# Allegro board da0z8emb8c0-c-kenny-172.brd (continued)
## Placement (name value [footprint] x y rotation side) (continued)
HOLE7  *spad-c354np  [SPAD-C354NP]  140.49 22.1 0 top
HOLE8  *HG-Z8E-EDADOC-3  [HG-Z8E-EDADOC-3]  86.2 15.5 0 top
HOLE10  EV@O-Z8E-1P2  [O-Z8E-1P2]  97.53 123.31 180 bottom
HOLE11  *hg-o335x315d252x232p2  [HG-O335X315D252X232P2]  11.25 109.2 180 bottom
HOLE13  *SPAD-A3A5-EDADOC-1  [SPAD-A3A5-EDADOC-1]  63.15 126.75 0 top
HOLE14  *H-TC154IC154BC237D154PT-1  [H-TC154IC154BC237D154PT-1]  78.57 83 0 top
HOLE15  EV@O-Z8E-1P2  [O-Z8E-1P2]  126.53 84.31 180 bottom
HOLE16  *hg-c354i158d118p2  [HG-C354I158D118P2]  17.48 68.15 180 bottom
HOLE17  *H-TC154IC154BC237D154PT-1  [H-TC154IC154BC237D154PT-1]  117.22 57 0 top
HOLE18  *HG-C276D126P2  [HG-C276D126P2]  221.2 48.5 180 bottom
HOLE19  *H-TC154IC154BC237D154PT-1  [H-TC154IC154BC237D154PT-1]  78.57 31 0 top
HOLE20  *h-c75d75n  [H-C75D75N]  4.2 24 180 bottom
HOLE21  h-davidoff-1  [H-DAVIDOFF-1]  216.8 21.88 180 bottom
HOLE22  *HG-Z8E-EDADOC-1  [HG-Z8E-EDADOC-1]  148.07 124.5 0 top
HOLE23  *H-DAVIDOFF-1-1  [H-DAVIDOFF-1-1]  5.2 4.4 180 bottom
HOLE24  *2D-BARCODE-8X8-S  [2D-BARCODE-8X8-S]  67.24 73.27 270 bottom
HOLE25  *2D-BARCODE-6X6-S  [2D-BARCODE-6X6-S]  21.27 99.94 0 top
HOLE26  *SPAD-RE3_5X5_0  [SPAD-RE3_5X5_0]  3.35 108.2 180 bottom
J1  *JUMP  [JOPEN25X30_S]  100.34 27.49 180 bottom
L6  BLM15AG121SN1D  [R0402]  166.18 31.86 270 top
L7  HCB2012KF-220T60  [R0805]  204.28 29.36 270 top
L9  BLM15AG121SN1D  [R0402]  186.62 16.24 180 top
L10  BLM15AG121SN1D  [R0402]  186.62 19.04 0 top
L11  BLM15AG601SN1D  [R0402]  41.08 103.49 90 bottom
L12  BLM15AG601SN1D  [R0402]  42.12 103.49 90 bottom
L13  HCB1608KF-121T30  [R0603]  204.28 19.54 270 bottom
L14  PBY160808T-600Y-N  [R0603]  201.74 18.15 180 bottom
L15  HCB1005KF-330T30  [R0402]  72.32 23.23 90 bottom
L16  HCB1005KF-330T30  [R0402]  75.5 23.23 90 bottom
NOREF  -  []  165.2 -14.93 0 top
NOREF#2  -  []  5.68 -31.69 0 top
NOREF#3  -  [unnamed#2]  39.81 112.76 0 top
NOREF#4  -  [unnamed#2]  14.29 3.42 0 top
NOREF#5  -  [unnamed#2]  216.6 44.31 0 top
NOREF#6  -  []  137.98 46 0 top
NOREF#7  -  [unnamed#2]  16.57 114.41 180 bottom
NOREF#8  -  [unnamed#2]  10.86 9 180 bottom
NOREF#9  -  [unnamed#2]  141.67 119.37 180 bottom
NOREF#10  -  []  170.11 31.52 180 bottom
PC1  1u/10V_4  [C0402]  65.68 125.08 90 top
PC2  10u/10V_4  [C0402_2]  66.75 125.08 270 top
PC3  0.1u/25V_4  [C0402]  68.7 125.09 270 top
PC6  0.047u/50V_6  [C0603]  44.26 120.03 0 top
PC7  *22u/6.3V_6  [C0603]  49.3 122.14 0 top
PC8  1000p/50V_4  [C0402]  41.21 121.4 180 top
PC10  0.1u/25V_4  [C0402]  68.69 121.79 90 top
PC11  10u/25V_6  [C0603]  72.7 122.14 270 top
PC12  10u/25V_6  [C0603]  71.29 122.14 270 top
PC14  2200p/50V_4  [C0402]  13.3 116.65 270 top
PC15  0.47u/10V_4  [C0402]  68.11 119.11 90 top
PC16  10u/6.3V_4  [C0402_2]  64.64 120.98 180 bottom
PC18  10u/6.3V_4  [C0402_2]  64.8 118.42 180 top
PC66  22u/6.3V_6  [C0603]  150.39 37.8 270 bottom
PC67  *22u/6.3V_6  [C0603]  157.52 34.64 270 bottom
PC69  *22u/6.3V_6  [C0603]  147.75 33.33 0 top
PC70  10p/50V_4  [C0402]  145.88 36.07 90 top
PC71  0.1u/16V_4  [C0402]  144.86 36.47 180 bottom
PC72  0.1u/16V_4  [C0402]  149.2 37.35 270 bottom
PC73  100p/50V_4  [C0402]  136.99 33.01 180 top
PC74  0.1u/50V_4  [C0402]  132.37 33.92 90 top
PC76  0.1u/50V_4  [C0402]  133.33 33.92 270 top
PC77  *100p/50V_4  [C0402]  136.99 32.05 180 top
PC78  0.1u/16V_4  [C0402]  20.89 30.47 180 top
PC79  0.1u/16V_4  [C0402]  143.93 35.22 90 top
PC80  2.2u/10V_4  [C0402]  131.99 30.58 90 top
PC81  10u/6.3V_6  [C0603]  21.78 29.83 180 bottom
PC82  1u/25V_4  [C0402]  22.67 30.42 0 top
PC86  2200p/50V_4  [C0402]  127.51 33.75 90 bottom
PC87  *0.1u/16V_4  [C0402]  25.21 29.32 180 top
PC88  1u/25V_4  [C0402]  157.12 29.86 90 top
PC90  1u/25V_4  [C0402]  152.73 29.86 90 top
PC91  *0.01u/50V_4  [C0402]  122.03 28.86 270 top
PC92  1000p/50V_4  [C0402]  19.24 28.13 0 top
PC93  0.1u/16V_4  [C0402]  25.21 28.31 180 top
PC96  0.01u/50V_4  [C0402]  134.08 28.56 90 top
PC98  1000p/50V_4  [C0402]  19.24 27.04 0 top
PC99  *0.1u/16V_4  [C0402]  25.21 27.29 180 top
PC101  1u/25V_4  [C0402]  25.21 26.28 180 top
PC103  0.1u/16V_4  [C0402]  21.91 25.69 180 top
PC104  *2200p/50V_4  [C0402]  69.78 89.01 0 bottom
PC105  10u/6.3V_6  [C0603]  21.27 27.8 270 bottom
PC106  10u/6.3V_6  [C0603]  157.41 26.78 180 top
PC108  0.1u/16V_4  [C0402]  157.54 28.05 180 top
PC109  0.1u/16V_4  [C0402]  152.72 27.82 270 top
PC110  1000p/50V_4  [C0402]  153.58 27.8 0 bottom
PC111  1000p/50V_4  [C0402]  156.26 27.8 180 bottom
PC112  10u/6.3V_6  [C0603]  151.54 28.27 270 top
PC113  22u/6.3V_6  [C0603]  31.38 15.74 90 bottom
PC114  *22u/6.3V_6  [C0603]  28.13 15.48 90 bottom
PC115  *680p/50V_6  [C0603]  44.56 22.32 180 bottom
PC116  0.1u/25V_4  [C0402]  41.49 16.67 0 bottom
PC117  2200p/50V_4  [C0402]  125.36 30.5 180 top
PC118  0.1u/50V_4  [C0402]  125.36 31.46 180 top
PC119  22u/6.3V_6  [C0603]  29.97 15.74 90 bottom
PC120  *22u/6.3V_6  [C0603]  35.88 15.02 0 bottom
PC121  22u/6.3V_6  [C0603]  32.79 15.82 90 bottom
PC122  *47p/50V_4  [C0402]  105.42 20.41 90 top
PC123  *47p/50V_4  [C0402]  103.69 21.32 90 top
PC125  *1u/10V_4  [C0402]  66.27 125.1 90 bottom
PC126  *1u/10V_4  [C0402]  68.66 125.11 90 bottom
PC128  *22u/6.3V_6  [C0603]  60.83 124.64 90 top
PC129  22u/6.3V_6  [C0603]  61.99 122.62 0 top
PC130  22u/6.3V_6  [C0603]  53.91 124.32 270 bottom
PC131  22u/6.3V_6  [C0603]  52.26 124.32 270 bottom
PC132  22u/6.3V_6  [C0603]  55.51 124.32 270 bottom
PC133  22u/6.3V_6  [C0603]  57.08 124.32 270 bottom
PC135  EV@0.1u/16V_4  [C0402]  120.33 83.81 180 bottom
PC136  *680p/50V_6  [C0603]  62.01 123.29 90 bottom
PC137  22u/6.3V_6  [C0603]  49.29 122.14 0 bottom
PC138  2200p/50V_4  [C0402]  69.07 120.07 270 top
PC139  0.1u/25V_4  [C0402]  59.93 119.75 0 top
PC140  10u/25V_6  [C0603]  69.87 122.24 270 top
PC142  *10u/6.3V_4  [C0402_2]  64.64 119.8 180 bottom
PC143  0.1u/50V_4  [C0402]  40.19 119.62 90 bottom
PC145  0.1u/50V_4  [C0402]  12.28 116.65 270 top
PC164  0.1u/16V_4  [C0402]  115.76 34.78 90 bottom
PC221  2200p/50V_4  [C0402]  140.44 29.62 180 bottom
PC224  22u/6.3V_6  [C0603]  147.75 30.51 0 top
PC225  22u/6.3V_6  [C0603]  147.75 31.92 0 top
PC226  22u/6.3V_6  [C0603]  151.8 37.8 270 bottom
PC227  4.7u/6.3V_4  [C0402_2]  146.31 36.09 270 bottom
PC229  0.1u/25V_4  [C0402]  148.17 35.95 90 bottom
PC233  10u/25V_8  [C0805]  140.84 32.04 0 bottom
PC234  1u/10V_4  [C0402]  144.86 35.51 0 bottom
PC235  100p/50V_4  [C0402]  138 33.97 180 top
PC236  2200p/50V_4  [C0402]  106.17 24.42 90 bottom
PC237  0.1u/50V_4  [C0402]  132.27 34.68 0 bottom
PC238  0.47u/25V_6  [C0603]  129.52 33.96 0 bottom
PC239  10u/25V_8  [C0805]  142.29 29.45 90 bottom
PC240  10u/25V_8  [C0805]  126.03 33.92 90 bottom
PC241  22u/25V_8  [C0805]  107.66 24.23 90 bottom
PC242  *0.1u/16V_4  [C0402]  135.44 29.15 0 top
PC243  0.047u/50V_6  [C0603]  129.52 32.55 0 bottom
PC244  0.1u/25V_4  [C0402]  140.44 30.58 180 bottom
PC245  0.1u/25V_4  [C0402]  138.65 40.83 270 top
PC246  22u/25V_8  [C0805]  110.26 23.6 0 bottom
PC247  *680p/50V_6  [C0603]  144.72 30.08 0 bottom
PC248  0.1u/25V_4  [C0402]  130.38 28.99 180 bottom
PC249  *680p/50V_6  [C0603]  127.03 29.23 270 bottom
PC250  *0.1u/16V_4  [C0402]  153.58 28.91 0 bottom
PC251  0.1u/16V_4  [C0402]  154.92 28.53 90 bottom
PC252  *0.1u/16V_4  [C0402]  156.65 29.83 180 bottom
PC253  0.1u/25V_4  [C0402]  128.77 28.16 270 bottom
PC254  0.1u/25V_4  [C0402]  130.38 27.78 180 bottom
PC256  0.1u/50V_4  [C0402]  104.25 24.42 270 bottom
PC258  *100p/50V_4  [C0402]  105.21 24.42 90 bottom
PC261  2200p/50V_4  [C0402]  47.39 15.69 90 bottom
PC262  0.1u/25V_4  [C0402]  46.84 18.94 270 bottom
PC263  0.1u/25V_4  [C0402]  47.8 18.94 90 bottom
PC264  10u/25V_8  [C0805]  49.27 19.62 270 bottom
PC265  1u/10V_4  [C0402]  43.73 15.8 90 bottom
PC266  4.7u/10V_4  [C0402]  43.05 19.38 270 top
PC267  0.1u/16V_4  [C0402]  46.43 15.46 90 bottom
PC268  0.1u/16V_4  [C0402]  32.19 24.98 90 bottom
PC269  22u/6.3V_6  [C0603]  31.97 22.79 270 bottom
PC270  10u/25V_8  [C0805]  47.29 21.42 270 bottom
PC271  0.1u/16V_4  [C0402]  46.66 17.35 0 bottom
PC272  10p/50V_4  [C0402]  45.09 15.08 0 bottom
PC551  *2200p/50V_6  [C0603]  37.02 23.56 0 top
PC561  0.1u/6.3V_2  [C0201]  34.35 25.01 270 top
PC562  22u/6.3V_6  [C0603]  32.95 27.93 270 top
PC563  22u/6.3V_6  [C0603]  34.48 27.93 270 top
PC571  10u/6.3V_4  [C0402_2]  44 27.29 270 top
PC572  0.01u/50V_4  [C0402]  45.27 27.29 270 top
PC574  *22p/50V_4  [C0402]  39.56 23.23 270 top
PC581  *0.1u/6.3V_2  [C0201]  39.18 25.51 0 top
PC2000  *0.01u/50V_4  [C0402]  145.33 39.58 270 bottom
PC2001  *0.1u/25V_4  [C0402]  146.69 40.83 90 top
PC2002  2200p/50V_4  [C0402]  145.73 40.83 90 top
PC2003  10u/25V_8  [C0805]  142.28 38.96 0 bottom
PC2004  10u/6.3V_6  [C0603]  143.12 46.24 0 bottom
PC2005  0.1u/25V_4  [C0402]  138.53 46.02 270 bottom
PC2006  22u/6.3V_6  [C0603]  136.74 47.27 0 bottom
PC2007  22u/6.3V_6  [C0603]  134.52 38.15 90 bottom
PC2008  22u/6.3V_6  [C0603]  133.83 47.27 180 bottom
PC2009  22u/6.3V_6  [C0603]  133.1 38.15 90 bottom
PC2010  22u/6.3V_6  [C0603]  137.34 38.15 90 bottom
PC2011  *22u/6.3V_6  [C0603]  135.93 38.15 90 bottom
PC2012  *22u/6.3V_6  [C0603]  131.69 38.15 90 bottom
PC2013  0.1u/16V_4  [C0402]  130.5 38.6 90 bottom
PC2014  *1000p/50V_4  [C0402]  147.38 40.25 90 bottom
PC2015  *680p/50V_6  [C0603]  139.36 37.53 180 bottom
PC2016  *0.047u/6.3V_2  [C0201]  146.87 44.54 90 bottom
PC2017  0.047u/6.3V_2  [C0201]  145.1 45.53 90 bottom
PC5357  EV@10u/6.3V_6  [C0603]  120.46 85.08 0 bottom
PC5359  EV@0.1u/16V_4  [C0402]  106.49 83.68 90 bottom
PC6000  *1000p/25V_2  [C0201]  144.78 56.08 270 bottom
PC6001  2.2u/10V_4  [C0402]  150.97 54.63 0 top
PC6002  2.2u/10V_4  [C0402]  141.07 54.39 180 top
PC6003  0.1u/25V_4  [C0402]  145.61 56.04 90 bottom
PC6004  0.1u/25V_4  [C0402]  141.07 55.35 0 top
PC6005  0.1u/16V_4  [C0402]  147.53 57.95 180 top
PC6006  0.1u/6.3V_2  [C0201]  146.45 56.01 270 bottom
PC6007  82p/50V_4  [C0402]  145.81 57.95 180 top
PC6008  150p/50V_4  [C0402]  146.04 57.86 180 bottom
PC6009  0.1u/25V_4  [C0402]  141.45 53.05 90 top
PC6010  1u/6.3V_4  [C0402]  147.28 55.92 90 bottom
PC6011  0.1u/16V_4  [C0402]  149.2 49.61 270 top
PC6012  0.1u/6.3V_2  [C0201]  148.55 51.1 0 bottom
PC6013  0.1u/25V_4  [C0402]  141.42 51.32 90 top
PC6014  0.1u/16V_4  [C0402]  147.85 49.23 0 top
PC6015  82p/50V_4  [C0402]  146.13 49.5 180 top
PC6016  150p/50V_4  [C0402]  146.61 47.85 270 bottom
PC6017  *100p/50V_4  [C0402]  149.25 51.94 0 bottom
PC6018  *82p/50V_4  [C0402]  146.96 51.72 0 bottom
PC6019  0.47uF/6.3V_2  [C0201]  148.84 52.78 180 bottom
PC6020  *100p/50V_4  [C0402]  148.92 54.57 0 bottom
PC6021  10u/25V_8  [C0805]  140.26 48.4 0 bottom
PC6022  10u/25V_8  [C0805]  143.53 49.94 180 bottom
PC6023  *10u/25V_8  [C0805]  143.53 47.97 180 bottom
PC6024  2200p/50V_4  [C0402]  136.62 60.15 0 top
PC6025  0.1u/25V_4  [C0402]  136.63 61.12 0 top
PC6026  *15u/25V_7343H1.9  [CC7343]  121.93 41.17 90 bottom
PC6027  330u/2V_7343H1.9  [CC7343]  123.81 50.67 270 bottom
PC6028  330u/2V_7343H1.9  [CC7343]  118.26 63.87 180 bottom
PC6029  330u/2V_7343H1.9  [CC7343]  116.11 70.97 90 bottom
PC6030  *330u/2V_7343H1.9  [CC7343]  132.13 52.49 0 top
PC6031  *2200p/50V_4  [C0402]  133.06 59.58 90 top
PC6032  10u/25V_8  [C0805]  138.54 55.78 0 bottom
PC6033  10u/25V_8  [C0805]  141.79 60.64 180 bottom
PC6034  *10u/25V_8  [C0805]  139.86 63.23 270 bottom
PC6035  2200p/50V_4  [C0402]  137.44 53.9 90 top
PC6036  0.1u/25V_4  [C0402]  138.97 49.66 0 top
PC6037  *22u/6.3V_6  [C0603]  101.53 58.63 180 top
PC6038  *22u/6.3V_6  [C0603]  99.12 58.13 90 top
PC6039  *22u/6.3V_6  [C0603]  100.77 60.44 180 top
PC6040  *22u/6.3V_6  [C0603]  98.11 54.47 180 top
PC6041  22u/6.3V_6  [C0603]  101.15 54.27 180 top
PC6042  22u/6.3V_6  [C0603]  101.53 57.11 180 top
PC6043  *22u/6.3V_6  [C0603]  99.5 52.69 180 top
PC6044  *22u/6.3V_6  [C0603]  104.23 57.01 90 top
PC6045  22u/6.3V_6  [C0603]  101.54 55.68 180 top
PC6046  22u/6.3V_6  [C0603]  105.65 57.01 90 top
PC6047  *2200p/50V_4  [C0402]  137.79 48.45 180 bottom
PC6048  10u/25V_8  [C0805]  125.9 68.83 270 bottom
PC6049  10u/25V_8  [C0805]  134.34 63.77 180 bottom
PC6050  *10u/25V_8  [C0805]  127.88 68.83 270 bottom
PC6051  2200p/50V_4  [C0402]  123.48 68.51 270 bottom
PC6052  0.1u/25V_4  [C0402]  124.44 68.51 270 bottom
PC6053  330u/2V_7343H1.9  [CC7343]  126.85 75.22 270 bottom
PC6054  *330u/2V_7343H1.9  [CC7343]  134.79 75.68 0 top
PC6055  *22u/6.3V_6  [C0603]  92.39 81.52 270 top
PC6056  *22u/6.3V_6  [C0603]  118.48 81.65 270 top
PC6057  *22u/6.3V_6  [C0603]  89.09 81.65 270 bottom
PC6058  *22u/6.3V_6  [C0603]  91.93 81.65 270 bottom
PC6059  *22u/6.3V_6  [C0603]  107.25 81.27 270 bottom
PC6060  *22u/6.3V_6  [C0603]  111.62 81.27 270 bottom
PC6061  *22u/6.3V_6  [C0603]  90.51 81.65 270 bottom
PC6062  *22u/6.3V_6  [C0603]  119.9 81.65 270 top
PC6063  *22u/6.3V_6  [C0603]  108.77 81.27 270 bottom
PC6064  *22u/6.3V_6  [C0603]  110.2 81.27 270 bottom
PC6065  *2200p/50V_4  [C0402]  139.09 73.9 270 bottom
PC6229  0.47u/6.3V_4  [C0402]  192.39 26.15 180 top
PC6230  10u/6.3V_6  [C0603]  195.26 16.12 90 top
PC6231  0.1u/16V_4  [C0402]  193.99 16.37 90 top
PC9000  EV@0.47uF/6.3V_2  [C0201]  66.93 112.36 180 bottom
PC9001  EV@2.2u/10V_4  [C0402]  66.49 114.18 180 bottom
PC9002  EV@2.2u/10V_4  [C0402]  78.13 112.52 0 bottom
PC9003  EV@0.1u/25V_4  [C0402]  76 116.43 270 bottom
PC9004  *SP@0.1u/25V_4  [C0402]  77.55 113.86 270 bottom
PC9005  *SP@0.1u/6.3V_2  [C0201]  71.64 116.04 180 bottom
PC9006  EV@0.1u/6.3V_2  [C0201]  72.32 118.55 270 bottom
PC9007  *SP@82p/50V_4  [C0402]  74.66 115.85 0 bottom
PC9008  *SP@150p/50V_4  [C0402]  74.59 117.77 0 bottom
PC9009  *EV@1000p/50V_4  [C0402]  75.93 118.46 90 bottom
PC9010  EV@0.1u/25V_4  [C0402]  78.13 111.26 180 bottom
PC9011  EV@1u/6.3V_2  [C0201]  71.18 117.21 180 bottom
PC9012  EV@0.1u/16V_4  [C0402]  68.92 107.08 270 bottom
PC9013  EV@0.1u/6.3V_2  [C0201]  68.52 103.94 0 bottom
PC9014  EV@0.1u/25V_4  [C0402]  76.4 107.57 0 bottom
PC9015  EV@0.1u/16V_4  [C0402]  70.85 107.08 90 bottom
PC9016  EV@82p/50V_4  [C0402]  73.1 106.97 270 bottom
PC9017  EV@150p/50V_4  [C0402]  72.91 105.21 270 bottom
PC9018  *EV@100p/50V_4  [C0402]  67.28 111.3 0 bottom
PC9019  *EV@82p/50V_4  [C0402]  74.06 107 270 bottom
PC9020  *EV@100p/50V_4  [C0402]  67.31 113.22 0 bottom
PC9021  EV@10u/25V_8  [C0805]  81.57 111.76 180 bottom
PC9022  EV@10u/25V_8  [C0805]  78.75 97.7 180 bottom
PC9023  *EV@10u/25V_8  [C0805]  76.46 95.73 180 bottom
PC9024  EV@2200p/50V_4  [C0402]  73.99 94.32 0 bottom
PC9025  EV@0.1u/25V_4  [C0402]  73.99 95.28 0 bottom
PC9026  EV@15u/25V_7343H1.9  [CC7343]  70.78 98.69 270 bottom
PC9027  EV@0.1u/16V_4  [C0402]  92.35 101.6 0 top
PC9028  EV@330u/2V_7343H1.9  [CC7343]  88.65 114.36 180 bottom
PC9029  EV@22u/6.3V_6  [C0603]  92.34 102.79 0 top
PC9031  *EV@2200p/50V_4  [C0402]  80.99 110.39 90 top
PC9032  EV@10u/25V_8  [C0805]  75.52 97.7 0 bottom
PC9033  EV@10u/25V_8  [C0805]  76.46 93.76 180 bottom
PC9034  *EV@10u/25V_8  [C0805]  81.57 113.74 180 bottom
PC9035  EV@2200p/50V_4  [C0402]  73.99 96.24 0 bottom
PC9036  EV@0.1u/25V_4  [C0402]  79.47 113.98 270 bottom
PC9037  *EV@330u/2V_7343H1.9  [CC7343]  90.25 107.29 180 top
PC9038  EV@0.1u/16V_4  [C0402]  92.35 100.63 0 top
PC9039  EV@330u/2V_7343H1.9  [CC7343]  82.82 94.37 180 bottom
PC9040  EV@22u/6.3V_6  [C0603]  92.34 104.21 0 top
PC9041  *EV@2200p/50V_4  [C0402]  81.27 98.18 0 bottom
PC9042  *SP@10u/25V_8  [C0805]  77.4 118.99 90 bottom
PC9043  *SP@10u/25V_8  [C0805]  80.51 119.86 90 top
PC9044  *SP@10u/25V_8  [C0805]  78.54 119.86 90 top
PC9045  *SP@2200p/50V_4  [C0402]  76.1 119.54 90 top
PC9046  *SP@0.1u/25V_4  [C0402]  77.06 119.54 90 top
PC9047  *SP@0.1u/16V_4  [C0402]  90.1 124.45 0 top
PC9049  *SP@330u/2V_7343H1.9  [CC7343]  87.68 121.46 180 top
PC9050  *SP@2200p/50V_4  [C0402]  82.07 116.28 0 top
PC9065  EV@2200p/50V_4  [C0402]  146.55 67.27 270 top
PC9066  *EV@22u/6.3V_6  [C0603]  141.82 75.05 90 bottom
PC9067  *EV@0.01u/50V_4  [C0402]  142.03 63.1 180 bottom
PC9068  *EV@680p/50V_6  [C0603]  142.43 68.55 180 bottom
PC9069  EV@22u/6.3V_6  [C0603]  147.17 74.48 90 top
PC9070  EV@22u/6.3V_6  [C0603]  145.76 74.48 90 top
PC9071  *EV@22u/6.3V_6  [C0603]  140.41 75.05 90 bottom
PC9072  EV@0.1u/25V_4  [C0402]  149.09 69.6 180 bottom
PC9073  EV@22u/6.3V_6  [C0603]  148.59 74.48 90 top
PC9074  EV@10u/6.3V_6  [C0603]  149.22 65.16 270 bottom
PC9075  *EV@0.1u/25V_4  [C0402]  145.59 67.27 270 top
PC9076  EV@22u/6.3V_6  [C0603]  144.35 74.48 90 top
PC9077  EV@0.047u/6.3V_2  [C0201]  148.51 63.41 0 bottom
PC9078  EV@0.1u/16V_4  [C0402]  149.11 77.66 180 bottom
PC9079  EV@22u/6.3V_6  [C0603]  142.87 74.5 90 top
PC9080  EV@10u/25V_8  [C0805]  141.94 66.15 270 bottom
PC9091  *EV@0.1u/16V_4  [C0402]  116.9 79.36 180 bottom
PC9092  EV@0.1u/16V_4  [C0402]  117.66 80.5 180 bottom
PC9094  EV@0.22u/10V_4  [C0402]  112.84 77.71 270 bottom
PC9095  *EV@1000p/50V_4  [C0402]  142.55 62.14 0 bottom
PC9096  *EV@0.047u/6.3V_2  [C0201]  147.77 61.68 0 bottom
PC9132  10u/6.3V_6  [C0603]  196.78 16.12 90 top
PC9162  *22p/50V_4  [C0402]  192.37 28.38 0 top
PC9163  *22u/6.3V_6  [C0603]  32.95 24.88 90 top
PC9164  4.7u/6.3V_4  [C0402_2]  196.56 31.53 270 top
PC9173  *10p/50V_4  [C0402]  150.16 55.92 270 bottom
PC9174  *10p/50V_4  [C0402]  149.2 55.92 270 bottom
PC9175  *10p/50V_4  [C0402]  148.24 55.92 270 bottom
PC9176  *EV@10p/50V_4  [C0402]  70.64 121.76 0 bottom
PC9177  *EV@10p/50V_4  [C0402]  70.93 119.84 0 bottom
PC9178  *EV@10p/25V_2  [C0201]  70.65 117.99 180 bottom
PC9179  EV@1u/6.3V_4  [C0402]  116.65 82.16 90 bottom
PC9181  EV@10u/6.3V_4  [C0402_2]  107.63 83.68 90 bottom
PC9182  EV@0.1u/16V_4  [C0402]  119.06 86.73 270 bottom
PC9183  *EV@10u/6.3V_4  [C0402_2]  108.9 83.68 90 bottom
PC9185  SP@0.1u/6.3V_2  [C0201]  94.3 115.3 0 top
PC9186  SP@22u/6.3V_6  [C0603]  91.88 116.19 0 top
PC9187  SP@22u/6.3V_6  [C0603]  112.94 109.08 0 top
PC9188  *22u/6.3V_6  [C0603]  116.39 109.59 270 top
PC9189  *22p/50V_4  [C0402]  87.44 117.33 90 top
PC9190  SP@0.01u/50V_4  [C0402]  85.79 113.65 90 top
PC9191  SP@10u/6.3V_4  [C0402_2]  84.64 113.65 90 top
PC9192  *0.1u/6.3V_2  [C0201]  90.1 116.32 90 top
PD2  P4SMAFJ20A  [D-3_8X2_5]  19.62 112.51 0 top
PD4  BAT54CW  [SOT23-1_7-65-3P]  127.22 33.46 270 top
PD5  PDZ5.6B  [D-SOD323-1_7X1_25-PMEG4005AEA]  107.62 21.1 0 top
PD6  PDZ5.6B  [D-SOD323-1_7X1_25-PMEG4005AEA]  101.41 21.58 180 top
PJ1  *Short_1206  [S1206]  72.64 119.1 0 top
PJ2  *Short_3720  [SHORT3720]  152.33 33.01 270 top
PJ3  *Short_3720  [SHORT3720]  140.84 34.82 0 bottom
PJ4  *Short_3720  [SHORT3720]  30.65 19.29 270 bottom
PJ5  *Short_1206  [S1206]  52.05 120.69 90 bottom
PJ6  30738-00042-001  [DCJK-30706-00042-001-3P-SMT]  1.85 116.6 90 bottom
PJ11  50458-00801-V02  [WTB-50458-00801-V02-8P-L]  102.45 16.42 180 bottom
PJ2000  *Short_3720  [SHORT3720]  128.1 45.96 270 bottom
PJ2001  *Short_3720  [SHORT3720]  142.78 39.9 180 top
PJ7002  *Short_3720  [SHORT3720]  195.9 19.8 270 top
PJ7004  *Short_3720  [SHORT3720]  30.16 26.53 90 top
PJ7005  *Short_3720  [SHORT3720]  45.78 24.12 90 top
PJ9001  *Short_3720  [SHORT3720]  75.3 102.55 90 bottom
PJ9007  *Short_3720  [SHORT3720]  143.17 65.28 270 top
PJ9008  *Short_3720  [SHORT3720]  144.03 78.35 180 top
PJ9010  *Short_3720  [SHORT3720]  50.08 16.19 180 bottom
PL1  4.7uH/1.08A_2.5x2.0x1.2  [L2_5X2-1_2]  63.23 124.65 180 top
PL2  0.68uH/15.5A_7x7x3  [L6_6X6_6-2_8H]  55.52 122.38 180 top
PL10  1uH/11A_7x7x3  [L6_6X6_6-2_8H]  152.2 32.94 0 bottom
PL11  6.8uH/4.5A_7x7x3  [L6_6X6_6-2_8H]  117.39 30.07 180 bottom
PL13  1uH/11A_7x7x3  [L6_6X6_6-2_8H]  37.05 19.3 180 bottom
PL14  2.2uH/1.67A_2.5x2.0x1.2  [L2_5X2-1_2H]  194.88 23.61 270 top
PL551  1uH/3.35A_2.5x2.0x1.2  [L2_5X2-1_2H]  36.84 27.42 180 top
PL2000  1uH/11A_7x7x3  [L6_6X6_6-2_8H]  134.5 43.01 180 bottom
PL6000  0.15uH/22A_7x7x3  [L6_6X6_6-2_8H]  133.81 75.17 180 bottom
PL6001  0.15uH/22A_7x7x3  [L6_6X6_6-2_8H]  127.61 60.01 180 bottom
PL6002  0.15uH/22A_7x7x3  [L6_6X6_6-2_8H]  130.76 52.83 180 bottom
PL9000  EV@0.22uH/23A_7x7x3  [L6_6X6_6-2_8H]  88.31 101.26 0 bottom
PL9001  EV@0.22uH/23A_7x7x3  [L6_6X6_6-2_8H]  89.79 108.45 0 bottom
PL9002  *SP@1uH/11A_7x7x3  [L6_6X6_6-2_8H]  88.45 120.28 0 bottom
PL9005  EV@1uH/11A_7x7x3  [L6_6X6_6-2_8H]  146.08 73.63 90 bottom
PL9006  SP@1uH/3.35A_2.5x2.0x1.2  [L2_5X2-1_2H]  92.01 113.91 0 top
PQ3  AONS32306  [POWER-5_67X4_8-1_27-5P]  39.05 117.97 0 top
PQ4  AONS32306  [POWER-5_67X4_8-1_27-5P]  47.18 116.57 180 top
PQ7  2N7002K  [SOT23-2-95-3P]  76.9 90.16 180 bottom
PQ8  DDTC144EUA-7-F  [SOT23-1_7-65-3P]  73.47 89.27 0 bottom
PQ9  2N7002KW  [SOT23-1_7-65-3P]  138.66 35.82 180 top
PQ10  2N7002K  [SOT23-2-95-3P]  125.79 37.71 180 top
PQ11  AONS32306  [POWER-5_2X5_55-1_27-5P]  118.73 32.04 270 top
PQ12  2N7002K  [SOT23-2-95-3P]  142.48 31.14 270 top
PQ13  2N7002K  [SOT23-2-95-3P]  47.48 16.12 90 top
PQ26  AONR32320C  [POWER-3X3-65-5P-ADNR21357]  123.02 34.28 270 bottom
PQ27  AONR32320C  [POWER-3X3-65-5P-ADNR21357]  124.14 30.14 0 bottom
PQ35  *2N7002K  [SOT23-2-95-3P]  62.15 90.54 0 bottom
PQ2000  AONS32306  [POWER-5_2X5_55-1_27-5P]  127.08 40.42 270 bottom
PQ6000  AONS36312  [POWER-5_2X5_55-1_27-5P]  137.65 68.23 270 bottom
PQ6001  AOE6932  [POWER-5X6-1_27-10P]  135.48 59.46 270 bottom
PQ6002  AOE6932  [POWER-5X6-1_27-10P]  138.62 52.09 270 bottom
PQ6003  AONS36380  [POWER-5_2X5_55-1_27-5P]  132.04 68.21 90 bottom
PQ9000  EV@AOE6932  [POWER-5X6-1_27-10P]  81.93 108.08 90 bottom
PQ9001  EV@AOE6932  [POWER-5X6-1_27-10P]  80.37 101.41 90 bottom
PQ9002  *SP@AONY36354  [POWER-5X6-1_27-7P-0_8H]  81.09 119.19 0 bottom
PQ9003  EV@AO3413  [SOT23-2_38-95-3P]  114.87 80.5 180 bottom
PQ9006  EV@2N7002K  [SOT23-2-95-3P]  110.55 78.29 270 bottom
PQ9007  EV@2N7002K  [SOT23-2-95-3P]  133.41 122.41 270 bottom
PQ9008  EV@2N7002K  [SOT23-2-95-3P]  129.86 122.16 90 bottom
PQ9013  2N7002K  [SOT23-2-95-3P]  62.18 86.98 180 bottom
PQ9014  AOSS32334C  [SOT23-2_38-95-3P]  26.35 31.86 90 top
PQ9015  2N7002K  [SOT23-2-95-3P]  67.51 86.98 180 bottom
PQ9056  *AOSS32334C  [SOT23-2_38-95-3P]  67.32 83.36 0 bottom
PQ9057  2N7002K  [SOT23-2-95-3P]  71.82 85.08 90 bottom
PQ9062  EV@2N7002K  [SOT23-2-95-3P]  144.33 70.73 0 top
PQ9063  EV@2N7002K  [SOT23-2-95-3P]  148.27 68.95 0 top
PQ9065  EV@2N7002K  [SOT23-2-95-3P]  92.9 96.76 180 top
PQ9066  EV@2N7002K  [SOT23-2-95-3P]  92.39 95.31 270 bottom
PQ9067  EV@2N7002K  [SOT23-2-95-3P]  130.24 118.48 90 bottom
PQ9068  EV@2N7002K  [SOT23-2-95-3P]  137.09 122.92 90 bottom
PQ9069  EV@2N7002K  [SOT23-2-95-3P]  130.24 118.35 90 top
PR2  *Short_0402  [S0402]  70.27 125.11 0 top
PR6  *Short_0603  [S0603]  62.1 118.65 180 top
PR8  *Short_0201  [S0201]  66.02 118.65 90 top
PR9  *Short_0402  [S0402]  69.45 118.73 180 top
PR12  0.01_1%_0612  [RC3216]  52.97 116.9 90 top
PR18  *Short_0201  [S0201]  52.67 114.45 90 top
PR19  *Short_0201  [S0201]  53.38 114.45 90 top
PR68  *Short_0603  [S0603]  148.72 36.28 90 top
PR69  1M_5%_6  [R0603]  136.44 34.8 90 top
PR70  10K_1%_4  [R0402]  145.3 34.73 180 top
PR71  1M_5%_6  [R0603]  132.41 37.36 180 top
PR72  1K_1%_4  [R0402]  146.23 37.45 0 top
PR74  100K_1%_4  [R0402]  134.29 33.92 90 top
PR75  100K_1%_4  [R0402]  134.09 35.27 180 top
PR76  *20.5K_1%_4  [R0402]  136.99 31.09 0 top
PR77  *Short_0201  [S0201]  144.75 33.89 180 top
PR78  *1K_1%_4  [R0402]  144.92 36.07 270 top
PR80  *Short_0201  [S0201]  135.41 35.66 90 bottom
PR81  20_5%_12  [R1206]  129.64 32.03 270 top
PR82  *100K_1%_2  [R0201]  142.81 29.07 180 top
PR83  10K_1%_4  [R0402]  143.76 33.2 270 top
PR84  *10K_1%_4  [R0402]  147.52 36.11 90 top
PR85  100K_5%_4  [R0402]  136.99 30.13 0 top
PR86  *0_5%_2  [R0201]  136.43 28.51 180 bottom
PR87  *Short_0805  [S0805]  18.48 29.09 0 bottom
PR88  0_5%_2  [R0201]  136.43 27.67 0 bottom
PR89  *Short_0201  [S0201]  27.11 29.32 180 top
PR90  1M_5%_4  [R0402]  102.33 23.14 180 bottom
PR92  *0_5%_2  [R0201]  141.75 28.97 270 top
PR93  *Short_0201  [S0201]  27.11 28.31 0 top
PR96  *Short_0201  [S0201]  141.04 28.97 270 top
PR97  100K_1%_4  [R0402]  133.12 28.56 270 top
PR98  316K_1%_4  [R0402]  135.42 28.18 180 top
PR99  *Short_0603  [S0603]  131.08 29.01 0 top
PR100  *Short_0201  [S0201]  27.11 27.29 0 top
PR102  22_5%_8  [R0805]  64.83 87.61 90 bottom
PR107  *Short_0805  [S0805]  149.16 27.55 0 top
PR108  10_1%_6  [R0603]  130.95 27.52 180 top
PR110  *Short_0805  [S0805]  153.58 25.16 180 top
PR111  *Short_0805  [S0805]  18.48 27.06 180 bottom
PR112  *0_5%_2  [R0201]  99.26 23.07 0 bottom
PR113  100_5%_4  [R0402]  100.61 23.14 180 bottom
PR114  *4.7_5%_6  [R0603]  41.94 22.16 180 bottom
PR115  10_1%_6  [R0603]  41.94 15.48 180 bottom
PR117  *Short_0603  [S0603]  45.09 18.65 0 top
PR118  *100K_1%_2  [R0201]  45.36 15.91 270 top
PR119  100_5%_4  [R0402]  105.79 23.08 180 bottom
PR120  100_5%_4  [R0402]  104.07 23.08 0 bottom
PR121  *0_5%_2  [R0201]  48.58 18.27 90 top
PR122  *Short_0201  [S0201]  49.34 18.27 90 top
PR123  *Short_0201  [S0201]  63.81 125.59 0 bottom
PR124  *Short_0201  [S0201]  67.11 124.8 90 bottom
PR125  *Short_0201  [S0201]  69.66 124.95 0 bottom
PR126  *0_5%_2  [R0201]  67.82 124.8 270 bottom
PR127  *Short_0805  [S0805]  58.88 123.75 90 bottom
PR128  *Short_0201  [S0201]  66.23 122.16 90 bottom
PR129  *4.7_5%_6  [R0603]  60.6 123.29 270 bottom
PR130  *Short_0603  [S0603]  62.75 119.65 270 bottom
PR131  100K_1%_2  [R0201]  65.47 122.16 90 bottom
PR132  5.1_1%_6  [R0603]  62.1 120.06 180 top
PR156  *Short_0805  [S0805]  120.58 81.9 180 bottom
PR159  EV@12.7K_1%_4  [R0402]  108.52 86.47 0 bottom
PR160  EV@10K_1%_4  [R0402]  108.52 87.49 0 bottom
PR161  *Short_0402  [S0402]  117.03 88.38 180 bottom
PR191  150_5%_4  [R0402]  110.42 31.1 180 bottom
PR193  *Short_0201  [S0201]  118.93 38.98 270 bottom
PR194  25.5K_1%_4  [R0402]  117.28 38.85 180 bottom
PR216  *220_5%_8  [R0805]  61.15 93.97 90 bottom
PR230  100K_1%_2  [R0201]  143.06 35.55 270 top
PR234  10K_1%_2  [R0201]  142.78 33.9 0 top
PR236  *Short_0201  [S0201]  148.99 38.75 0 bottom
PR237  *Short_0201  [S0201]  142.76 33.16 180 top
PR239  10_1%_6  [R0603]  147.41 37.66 0 bottom
PR244  *Short_0201  [S0201]  143.59 35.53 90 bottom
PR245  866K_1%_4  [R0402]  136.25 35.06 90 bottom
PR246  137K_1%_4  [R0402]  135.25 33.92 270 top
PR247  4.02K_1%_4  [R0402]  134.58 35.06 90 bottom
PR248  4.02K_1%_4  [R0402]  133.62 35.06 90 bottom
PR249  *Short_0201  [S0201]  137.22 34.86 0 bottom
PR250  *Short_0201  [S0201]  137.76 33.86 0 bottom
PR251  *Short_0201  [S0201]  137.76 33.15 0 bottom
PR252  *100K_1%_2  [R0201]  138.36 29.16 180 top
PR253  *Short_0201  [S0201]  137.76 31.95 0 bottom
PR254  *Short_0603  [S0603]  129.52 31.06 0 bottom
PR255  *Short_0201  [S0201]  137.76 31.24 0 bottom
PR257  *Short_0201  [S0201]  157.41 30.72 0 bottom
PR258  *4.7_5%_6  [R0603]  147.34 30.08 0 bottom
PR259  *Short_0201  [S0201]  151.78 29.01 0 bottom
PR260  *Short_0201  [S0201]  155.89 28.94 0 bottom
PR261  *Short_0201  [S0201]  131.75 28.5 0 bottom
PR264  10K_5%_4  [R0402]  138.21 29.06 180 bottom
PR265  *10K_5%_4  [R0402]  138.21 30.02 180 bottom
PR266  0.01_1%_0612  [RC3216]  111.94 26.32 180 bottom
PR267  *Short_0201  [S0201]  131.75 27.79 0 bottom
PR268  *4.7_5%_6  [R0603]  123.73 27.36 180 bottom
PR270  *Short_0201  [S0201]  115.71 26.16 0 bottom
PR271  *Short_0201  [S0201]  114.62 25.77 0 bottom
PR273  *Short_0201  [S0201]  47.42 14.03 0 bottom
PR274  *1K_1%_4  [R0402]  44.33 14.12 0 bottom
PR275  *10K_1%_4  [R0402]  45.09 16.04 0 bottom
PR276  *Short_0201  [S0201]  47.81 18.27 90 top
PR277  *Short_0201  [S0201]  41.21 14.21 0 bottom
PR278  1K_1%_4  [R0402]  46.05 14.12 180 bottom
PR279  10K_1%_4  [R0402]  44.4 16.62 270 top
PR283  15K_1%_2  [R0201]  193.99 30.72 90 top
PR284  *Short_0201  [S0201]  195.26 30.59 90 top
PR551  *2.2_5%_6  [R0603]  37.02 25.01 0 top
PR566  *Short_0402  [S0402]  39.43 24.62 180 top
PR567  10K_1%_4  [R0402]  41.97 23.99 0 top
PR568  20K_1%_2  [R0201]  40.57 23.23 90 top
PR569  *Short_0201  [S0201]  35.11 25.01 90 top
PR2000  100K_1%_2  [R0201]  145.96 45.43 0 bottom
PR2001  73.2K_1%_4  [R0402]  144.37 39.08 90 bottom
PR2002  10_5%_4  [R0402]  145.29 46.5 0 bottom
PR2003  2.2_5%_6  [R0603]  140.32 46.24 180 bottom
PR2004  *Short_0201  [S0201]  146.14 44.56 90 bottom
PR2005  *0_5%_2  [R0201]  147.51 43.5 90 bottom
PR2006  *Short_0201  [S0201]  146.54 43.5 270 bottom
PR2007  *4.7_5%_6  [R0603]  138.75 39.55 90 bottom
PR2008  10_1%_2  [R0201]  130.26 37.2 90 bottom
PR2009  *Short_0402  [S0402]  147.47 46.12 90 bottom
PR2010  11.8K_1%_4  [R0402]  146.31 41.16 270 bottom
PR2011  20K_1%_2  [R0201]  147.38 41.54 0 bottom
PR2012  *Short_0201  [S0201]  129.35 35.67 270 bottom
PR2013  *Short_0402  [S0402]  147.02 42.5 180 bottom
PR2015  *0_5%_2  [R0201]  119.19 50.53 90 top
PR2033  *10K_1%_2  [R0201]  151.06 56.63 270 bottom
PR6000  *Short_0201  [S0201]  113.47 54.22 270 bottom
PR6001  4.7_5%_4  [R0402]  150.97 53.67 0 top
PR6002  *Short_0402  [S0402]  140.08 50.62 180 top
PR6003  4.7_5%_4  [R0402]  144.69 58.07 90 bottom
PR6004  1.47K_1%_4  [R0402]  153.12 49.56 0 top
PR6005  28K_1%_4  [R0402]  151.4 49.56 0 top
PR6006  19.1K_1%_4  [R0402]  150.94 52.57 0 top
PR6007  22.6K_1%_4  [R0402]  152.72 52.41 180 bottom
PR6008  1_5%_6  [R0603]  141.52 56.54 180 top
PR6009  590_1%_4  [R0402]  152.66 50.65 0 top
PR6010  4.53K_1%_4  [R0402]  150.94 50.65 0 top
PR6011  237K_1%_4  [R0402]  152.66 52.57 0 top
PR6012  *Short_0201  [S0201]  134.15 79.21 270 bottom
PR6013  60.4K_1%_4  [R0402]  132.81 80.16 0 bottom
PR6014  *Short_0603  [S0603]  139.5 55.93 90 top
PR6015  3.74K_1%_4  [R0402]  147.53 59.87 180 top
PR6016  10K_1%_4  [R0402]  152.66 51.61 180 top
PR6017  14K_1%_4  [R0402]  150.94 51.61 180 top
PR6018  100K_NTC_4_1%  [R0402]  132.81 79.2 0 bottom
PR6019  6.04K_1%_4  [R0402]  152.84 50.41 0 bottom
PR6020  60.4K_1%_4  [R0402]  151.17 50.36 270 bottom
PR6021  *Short_0201  [S0201]  129.96 48.78 90 bottom
PR6022  60.4K_1%_4  [R0402]  127.02 48.79 180 bottom
PR6023  1.43K_1%_4  [R0402]  147.53 58.91 180 top
PR6024  11K_1%_4  [R0402]  152.72 51.42 0 bottom
PR6025  100K_NTC_4_1%  [R0402]  128.74 48.79 0 bottom
PR6026  24.9K_1%_4  [R0402]  145.81 58.91 180 top
PR6027  10K_1%_4  [R0402]  146.04 58.82 180 bottom
PR6028  *Short_0402  [S0402]  144.47 58.56 90 top
PR6029  100_1%_4  [R0402]  129.73 80.02 270 bottom
PR6030  *Short_0201  [S0201]  123.51 80.38 0 bottom
PR6031  1_5%_6  [R0603]  139.45 60.31 270 bottom
PR6032  *Short_0201  [S0201]  144.21 51.55 270 bottom
PR6033  *Short_0603  [S0603]  140.23 52.41 270 top
PR6034  2.2_5%_6  [R0603]  147.61 58.76 90 bottom
PR6035  *1K_1%_4  [R0402]  150.11 47.95 0 bottom
PR6036  3.74K_1%_4  [R0402]  151.24 48.91 180 bottom
PR6037  *Short_0201  [S0201]  150.4 55.6 90 top
PR6038  1.43K_1%_4  [R0402]  149.52 49.3 180 bottom
PR6039  *Short_0201  [S0201]  150.54 56.45 0 top
PR6040  1_1%_4  [R0402]  149.83 50.26 180 bottom
PR6041  *Short_0201  [S0201]  150.54 57.21 0 top
PR6042  1_5%_6  [R0603]  142.94 52.35 270 bottom
PR6043  *Short_0603  [S0603]  142.25 49.76 0 top
PR6044  *Short_0201  [S0201]  149.06 57.81 90 top
PR6045  3.74K_1%_4  [R0402]  148.45 46.61 90 bottom
PR6046  1.43K_1%_4  [R0402]  147.8 49.3 0 bottom
PR6047  1_1%_4  [R0402]  148.39 47.95 180 bottom
PR6048  10K_1%_2  [R0201]  144.06 49.11 180 top
PR6049  *Short_0201  [S0201]  144.06 49.82 180 top
PR6050  *1K_1%_4  [R0402]  149.41 46.61 90 bottom
PR6051  *Short_0201  [S0201]  150.18 49.52 270 top
PR6052  54.9K_1%_4  [R0402]  146 49.47 180 bottom
PR6053  10K_1%_4  [R0402]  145.65 47.85 270 bottom
PR6054  1K_1%_4  [R0402]  150.97 51.7 0 bottom
PR6055  100_1%_4  [R0402]  120.97 53.27 90 bottom
PR6056  *Short_0402  [S0402]  147.14 50.76 0 bottom
PR6057  100K_NTC_4_1%  [R0402]  131.43 48.78 0 bottom
PR6058  10.2K_1%_4  [R0402]  150.97 52.66 180 bottom
PR6059  10K_1%_4  [R0402]  154.49 50.28 90 top
PR6060  3.9_1%_4  [R0402]  148.87 53.61 0 bottom
PR6061  *Short_0201  [S0201]  112.71 54.72 270 bottom
PR6062  16.2K_1%_4  [R0402]  152.97 49.39 180 bottom
PR6063  16.5K_1%_4  [R0402]  150.97 53.62 180 bottom
PR6064  100_1%_4  [R0402]  145.62 51.36 270 bottom
PR6065  100K_NTC_4_1%  [R0402]  131.09 79.2 0 bottom
PR6066  13K_1%_4  [R0402]  150.97 54.58 0 bottom
PR6067  *2.2_5%_6  [R0603]  131.86 59.25 270 top
PR6068  *Short_0201  [S0201]  151.57 48.07 180 bottom
PR6069  *Short_0201  [S0201]  150.32 45.82 90 bottom
PR6070  *2.2_5%_6  [R0603]  135.62 48.68 180 bottom
PR6071  *Short_0201  [S0201]  148.39 45.25 90 bottom
PR6072  *Short_0201  [S0201]  150.46 47.11 180 bottom
PR6073  *2.2_5%_6  [R0603]  138.67 72.31 180 bottom
PR6074  *Short_0201  [S0201]  146.31 59.9 90 top
PR6075  *Short_0201  [S0201]  148.78 59.8 270 top
PR6414  *Short_0201  [S0201]  192.97 22.72 0 top
PR6416  100K_1%_2  [R0201]  195.26 31.61 270 top
PR6417  *Short_0402  [S0402]  192.77 24.75 270 top
PR6418  22.6K_1%_4  [R0402]  192.37 29.45 180 top
PR9000  *EV@1K_1%_4  [R0402]  69.89 107.08 90 bottom
PR9001  EV@4.7_5%_4  [R0402]  68.21 114.18 0 bottom
PR9002  *Short_0402  [S0402]  78.51 113.86 270 bottom
PR9003  EV@4.7_5%_4  [R0402]  79.47 111.64 270 bottom
PR9004  EV@487_1%_4  [R0402]  67.28 109.38 180 bottom
PR9005  EV@105K_1%_4  [R0402]  69 109.38 180 bottom
PR9006  *SP@1_5%_6  [R0603]  77.07 121.93 180 bottom
PR9007  EV@140_1%_4  [R0402]  67.28 110.34 180 bottom
PR9008  *SP@237K_1%_4  [R0402]  66.49 118.02 180 bottom
PR9009  *SP@60.4K_1%_4  [R0402]  89.99 125.32 180 bottom
PR9010  *Short_0603  [S0603]  77.46 116.07 90 bottom
PR9011  *SP@9.53K_1%_4  [R0402]  73.25 118.43 90 bottom
PR9012  *SP@10K_1%_4  [R0402]  66.49 115.14 0 bottom
PR9013  *SP@14K_1%_4  [R0402]  68.21 115.14 0 bottom
PR9014  EV@6.04K_1%_4  [R0402]  66.49 117.06 180 bottom
PR9015  *Short_0201  [S0201]  89.67 97.22 90 bottom
PR9016  EV@18.2K_1%_4  [R0402]  69 110.34 180 bottom
PR9017  *SP@19.1K_1%_4  [R0402]  68.21 118.02 180 bottom
PR9018  *SP@0_5%_2  [R0201]  88.77 125.33 90 bottom
PR9019  *SP@100K_NTC_4_1%  [R0402]  89.99 124.36 180 bottom
PR9020  EV@60.4K_1%_4  [R0402]  68.21 117.06 180 bottom
PR9021  EV@60.4K_1%_4  [R0402]  88.46 96.27 0 bottom
PR9022  *SP@1.69K_1%_4  [R0402]  72.58 117.08 0 bottom
PR9023  EV@11K_1%_4  [R0402]  66.49 116.1 180 bottom
PR9024  EV@22.6K_1%_4  [R0402]  68.21 116.1 0 bottom
PR9025  EV@100K_NTC_4_1%  [R0402]  88.46 97.23 0 bottom
PR9026  *SP@60.4K_1%_4  [R0402]  74.66 116.81 0 bottom
PR9027  *SP@10K_1%_4  [R0402]  74.59 118.73 0 bottom
PR9028  EV@100_1%_4  [R0402]  91.48 124.83 270 top
PR9029  *SP@0_5%_4  [R0402]  74.23 122.67 90 bottom
PR9030  EV@1_5%_6  [R0603]  77.96 106.85 90 bottom
PR9031  *Short_0603  [S0603]  77.96 109.47 270 bottom
PR9032  EV@2.2_5%_6  [R0603]  72.89 121.84 90 bottom
PR9033  EV@6.65K_1%_4  [R0402]  67 107.08 270 bottom
PR9034  *Short_0201  [S0201]  69.43 113.63 90 bottom
PR9035  EV@1.4K_1%_4  [R0402]  67.96 107.08 270 bottom
PR9036  *Short_0201  [S0201]  69.44 115.4 90 bottom
PR9037  EV@1_1%_4  [R0402]  68.89 105.74 0 bottom
PR9038  *Short_0201  [S0201]  69.93 116.38 90 bottom
PR9039  EV@1_5%_6  [R0603]  75.8 99.4 180 bottom
PR9040  *Short_0603  [S0603]  75.95 106.38 180 bottom
PR9041  *Short_0201  [S0201]  70.64 115.87 90 bottom
PR9042  EV@6.65K_1%_4  [R0402]  70.61 104.78 0 bottom
PR9043  EV@10K_1%_2  [R0201]  75.95 105.32 180 bottom
PR9044  EV@1.4K_1%_4  [R0402]  70.61 105.74 0 bottom
PR9045  EV@1_1%_4  [R0402]  68.89 104.78 0 bottom
PR9046  *Short_0201  [S0201]  74.92 107.68 270 bottom
PR9047  *EV@1K_1%_4  [R0402]  65.52 105.9 180 bottom
PR9048  *Short_0201  [S0201]  125.66 123.43 0 top
PR9049  EV@34K_1%_4  [R0402]  72.14 106.97 270 bottom
PR9050  EV@10K_1%_4  [R0402]  71.95 105.21 270 bottom
PR9051  EV@1K_1%_4  [R0402]  69 111.3 0 bottom
PR9052  EV@100_1%_4  [R0402]  85.61 91.5 0 bottom
PR9053  *Short_0402  [S0402]  74.35 105.19 180 bottom
PR9054  EV@100K_NTC_4_1%  [R0402]  86.74 97.23 0 bottom
PR9055  *Short_0201  [S0201]  84.24 91.49 0 bottom
PR9056  EV@11K_1%_4  [R0402]  69 108.42 0 bottom
PR9057  *SP@13.3K_1%_4  [R0402]  68.08 119.03 180 bottom
PR9058  EV@3.9_1%_4  [R0402]  68.29 112.26 0 bottom
PR9059  *Short_0201  [S0201]  83.21 91.49 180 bottom
PR9060  EV@17.4K_1%_4  [R0402]  67.28 108.42 180 bottom
PR9061  *SP@13K_1%_4  [R0402]  66.36 119.03 0 bottom
PR9062  EV@100_1%_4  [R0402]  81.82 91.5 0 bottom
PR9063  *SP@100K_NTC_4_1%  [R0402]  92.9 117.21 0 bottom
PR9064  *SP@7.32K_1%_4  [R0402]  66.36 119.99 0 bottom
PR9065  *EV@2.2_5%_6  [R0603]  82.78 110.87 0 top
PR9066  *Short_0201  [S0201]  65.82 107.02 0 bottom
PR9067  *Short_0201  [S0201]  67.25 105.85 0 bottom
PR9068  *EV@2.2_5%_6  [R0603]  83.44 97.98 0 bottom
PR9069  *Short_0201  [S0201]  69.53 103.94 180 bottom
PR9070  *Short_0201  [S0201]  71 103.94 180 bottom
PR9071  *SP@2.2_5%_6  [R0603]  82.23 118.07 90 top
PR9072  *Short_0201  [S0201]  73.21 119.67 0 bottom
PR9073  *Short_0201  [S0201]  72.32 119.54 270 bottom
PR9100  SP@10K_1%_2  [R0201]  73.32 115.71 270 bottom
PR9101  SP@10K_1%_2  [R0201]  72.55 115.71 270 bottom
PR9102  *SP@0_5%_2  [R0201]  71.64 115.33 0 bottom
PR9103  SP@100K_1%_2  [R0201]  84.52 115.3 90 top
PR9104  *Short_0201  [S0201]  85.28 115.3 90 top
PR9105  *Short_0201  [S0201]  89.09 116.41 270 top
PR9106  SP@11.8K_1%_4  [R0402]  86.42 117.33 90 top
PR9107  SP@20K_1%_4  [R0402]  85.41 117.33 270 top
PR9108  *Short_0201  [S0201]  88.45 117.84 0 top
PR9116  *Short_0201  [S0201]  146.76 62.04 0 bottom
PR9117  *Short_0402  [S0402]  145.76 61.76 90 bottom
PR9118  *Short_0402  [S0402]  148.91 60.82 0 bottom
PR9119  *Short_0201  [S0201]  147.85 62.39 180 bottom
PR9120  EV@105K_1%_4  [R0402]  142.03 64.06 0 bottom
PR9121  EV@10_5%_4  [R0402]  149.57 62.93 270 bottom
PR9122  EV@100K_1%_2  [R0201]  148.72 62.56 270 bottom
PR9123  *EV@4.7_5%_6  [R0603]  141.82 70.57 90 bottom
PR9124  *EV@0_5%_2  [R0201]  146.76 61.33 180 bottom
PR9125  EV@6.49K_1%_4  [R0402]  143.89 61.76 270 bottom
PR9126  EV@9.31K_1%_2  [R0201]  144.85 61.92 270 bottom
PR9128  EV@1M_5%_6  [R0603]  132.04 122.54 270 top
PR9129  EV@22_5%_8  [R0805]  126.81 122.16 90 bottom
PR9132  -  [R0402]  116.9 78.35 0 bottom
PR9133  *EV@10K_1%_4  [R0402]  114.82 77.71 90 bottom
PR9134  EV@20K_1%_2  [R0201]  113.83 77.71 90 bottom
PR9135  EV@1M_5%_6  [R0603]  133.54 122.54 90 top
PR9136  *EV@100K_1%_6  [R0603]  116.62 77.08 180 bottom
PR9137  EV@2.2_5%_6  [R0603]  149.25 67.81 90 bottom
PR9282  *Short_0603  [S0603]  197.93 31.36 90 top
PR9283  100K_1%_2  [R0201]  43.24 23.99 270 top
PR9284  1M_5%_6  [R0603]  71.18 90.83 90 bottom
PR9285  22_5%_8  [R0805]  80.2 90.03 0 bottom
PR9286  22_5%_8  [R0805]  129.09 37.96 0 top
PR9287  *100K_1%_6  [R0603]  73.72 91.3 0 bottom
PR9288  1M_5%_6  [R0603]  70.58 87.74 0 bottom
PR9289  1M_5%_6  [R0603]  69.66 90.83 90 bottom
PR9290  *Short_0201  [S0201]  43.06 25.77 270 top
PR9292  *Short_0201  [S0201]  138.81 29.95 180 top
PR9295  10_1%_2  [R0201]  128.46 35.67 90 bottom
PR9296  *Short_0201  [S0201]  118.17 50.41 0 top
PR9298  *0_5%_2  [R0201]  148.27 40.25 90 bottom
PR9300  10_1%_2  [R0201]  66.74 118.63 90 top
PR9301  49.9_1%_2  [R0201]  67.63 117.84 0 top
PR9304  *53.6K_1%_4  [R0402]  74.59 119.69 180 bottom
PR9305  *EV@10K_1%_4  [R0402]  71.2 122.72 0 bottom
PR9306  EV@10K_1%_4  [R0402]  70.93 118.88 0 bottom
PR9308  EV@10K_1%_4  [R0402]  69.59 118.3 90 bottom
PR9309  *EV@10K_1%_4  [R0402]  70.93 120.8 180 bottom
PR9310  *Short_0402  [S0402]  69.59 120.42 90 bottom
PR9311  22_5%_8  [R0805]  70.94 82.41 180 bottom
PR77835  *Short_0402  [S0402]  72.83 124.07 180 bottom
PR77846  *EV@0_5%_4  [R0402]  121.09 86.73 90 bottom
PR77847  -  [R0402]  118.81 88.38 180 bottom
PR77848  *Short_0805  [S0805]  106.49 86.35 90 bottom
PR77849  *Short_0201  [S0201]  92.34 125.44 90 top
PR77850  EV@1M_5%_6  [R0603]  141.92 70.98 270 top
PR77851  EV@22_5%_8  [R0805]  148.27 71.74 0 top
PR77852  EV@1M_5%_6  [R0603]  142.25 68.24 180 top
PR77853  *Short_0402  [S0402]  149.29 65.65 270 top
PR77854  EV@1M_5%_6  [R0603]  90.51 97.14 90 top
PR77855  EV@22_5%_8  [R0805]  96.17 96.76 0 top
PR77857  EV@1M_5%_6  [R0603]  89.09 97.14 270 top
PR77858  *Short_0402  [S0402]  95.06 94.6 0 bottom
PR77859  EV@1M_5%_6  [R0603]  135.06 122.54 270 top
PR77860  EV@22_5%_8  [R0805]  127.32 118.22 90 bottom
PR77861  EV@1M_5%_6  [R0603]  133.41 120.51 180 top
PR77862  *Short_0402  [S0402]  135.06 125.21 180 bottom
PR77863  EV@22_5%_8  [R0805]  127.32 118.22 90 top
PR77864  *Short_0402  [S0402]  120.08 86.73 90 bottom
PR77865  SP@0_5%_4  [R0402]  75.25 122.67 90 bottom
PR77866  *EV@10K_1%_2  [R0201]  124.52 123.43 0 top
PU1  TPS51486RJER  [QFN18-3X3-5]  65.51 121.24 0 top
PU6  AOZ1331ADI  [DFN14-3X2-4-11P-0_8H]  22.24 28.05 90 top
PU7  AOZ1331ADI  [DFN14-3X2-4-11P-0_8H]  154.93 29.02 180 top
PU9  EV@UP8801SSW8  [SOP8-6-1_27-9P-G5795F11U]  113.98 85.46 270 bottom
PU11  RT6256BGQUF  [QFN12-3X3-45-0_6H]  145.29 32.74 270 bottom
PU12  BQ24780SRUYR  [QFN28-4X4-4-38P]  134.22 31.18 0 bottom
PU15  RT6258CGQUF  [QFN12-3X3-45-0_6H]  44 18.96 90 bottom
PU2000  G5334CQT1U  [QFN23-4X4-5-25P]  142.97 42.74 270 bottom
PU3003  JW5222RSOTB_TRPBF  [SOT23-2_8-95-6P-1_1H]  195.26 27.42 270 top
PU3004  JW5213DFND_TRPBF  [DFN8-2X2-5-9P-MAX8902B]  40.47 27.34 90 top
PU6000  RT3662AMGQW  [QFN40-5X5-4-41P-RT3662AC]  146.35 53.7 0 top
PU9000  EV@RT3662AMGQW  [QFN40-5X5-4-41P-RT3662AC]  73.55 111.68 180 bottom
PU9005  EV@G5335QT2U  [QFN23-4X4-5-25P]  145.72 65.54 180 bottom
PU9006  TMP708AIDBVR  [SOT23-2_8-95-5P-LP2985-50DBVT]  117.92 36.05 90 bottom
PU9007  SP@JW5213DFND_TRPBF  [DFN8-2X2-5-9P-MAX8902B]  88.33 114.29 270 top
Q2  AO3413  [SOT23-2_38-95-3P]  53.53 110.98 270 top
Q3  DDTC144EUA-7-F  [SOT23-1_7-65-3P]  56.7 110.6 90 top
Q4  2N7002KDW  [SOT363-2_1-65-6P]  56.58 102.48 270 top
Q6  2N7002K  [SOT23-2-95-3P]  59.49 99.55 0 top
Q7  PJA138K  [SOT23-2-95-3P]  63.94 97.37 90 top
Q14  METR3904-G  [SOT23-2-95-3P]  103.77 29.4 180 top
Q16  METR3904-G  [SOT23-2-95-3P]  175.45 21.96 270 bottom
Q18  2N7002KTB  [SOT23-1_38-5-3P]  180.53 20.05 0 bottom
Q19  *PBA@DMP2130L-7  [SOT23-2-95-3P]  52.03 19.82 180 bottom
Q20  2N7002K  [SOT23-2-95-3P]  149.16 14.72 90 top
Q21  2N7002KDW  [SOT363-2_1-65-6P]  71.63 17.72 180 top
Q33  AP2331SA-7  [SOT23-2-95-3P]  14.67 85.97 180 top
Q43  *2N7002K  [SOT23-2-95-3P]  68.69 24.57 180 bottom
Q44  *KBL@DDTC144EUA-7-F  [SOT23-1_7-65-3P]  195.08 17.33 180 bottom
Q45  *PJA138K  [SOT23-2-95-3P]  196.78 20.31 90 bottom
Q46  *2N7002KTB  [SOT23-1_38-5-3P]  180.66 15.99 90 bottom
Q47  *KBL@DMP2130L-7  [SOT23-2-95-3P]  197.8 14.59 90 bottom
Q2025  2N7002K  [SOT23-2-95-3P]  101.61 32.94 0 top
Q2030  *EV@2N7002KTB  [SOT23-1_38-5-3P]  104.58 82.54 180 bottom
Q2031  DMN5L06DWK-7  [SOT363-2_1-65-6P-DMC2004DWK-7]  109.41 74.89 180 bottom
Q2032  DMN5L06DWK-7  [SOT363-2_1-65-6P-DMC2004DWK-7]  115 37.83 270 bottom
Q2033  2N7002K  [SOT23-2-95-3P]  107 77.96 0 bottom
Q2038  EV@2N7002KDW  [SOT363-2_1-65-6P]  108.01 123.99 0 bottom
Q2039  *TPC@2N7002K  [SOT23-2-95-3P]  24.83 21.83 270 top
Q5403  2N7002K  [SOT23-2-95-3P]  207.83 19.29 270 bottom
Q6544  *METR3904-G  [SOT23-2-95-3P]  102.55 78.42 180 bottom
Q6565  *DMN5L06DWK-7  [SOT363-2_1-65-6P-DMC2004DWK-7]  111.31 16.88 0 top
R4  *Short_0805  [S0805]  50.1 109.46 0 top
R5  100K_5%_2  [R0201]  52 107.17 270 top
R6  2.49K_1%_4  [R0402]  42.23 111.37 90 top
R7  *2.2_1%_0805  [R0805]  50.73 112.13 270 top
R8  75_1%_8  [R0805]  31.68 111.62 90 top
R9  75_1%_8  [R0805]  28.76 111.52 90 top
R10  75_1%_8  [R0805]  34.73 111.37 90 top
R11  75_1%_8  [R0805]  37.53 111.37 90 top
R12  *1K_5%_2  [R0201]  57.72 106.41 180 top
R13  10K_5%_2  [R0201]  56.83 108.7 0 top
R14  10K_5%_2  [R0201]  51.24 107.17 90 top
R15  680_5%_4  [R0402]  44.77 109.46 270 top
R16  10_5%_2  [R0201]  45.65 109.84 270 top
R18  *100K_1%_2  [R0201]  54.04 105.27 270 bottom
R19  100K_5%_2  [R0201]  57.72 107.17 0 top
R20  *Short_0201  [S0201]  56.83 105.29 0 top
R21  *1K_5%_2  [R0201]  54.29 107.17 90 top
R22  *100K_1%_2  [R0201]  55.18 105.27 270 bottom
R23  *100K_1%_2  [R0201]  52.77 107.17 270 top
R24  10K_5%_2  [R0201]  57.45 100.57 0 top
R25  10_5%_2  [R0201]  53.53 107.17 90 top
R26  1K_1%_2  [R0201]  55.05 107.17 270 top
R27  100K_1%_2  [R0201]  55.81 107.17 90 top
R28  *Short_0201  [S0201]  56.83 104.56 0 top
R30  15K_1%_4  [R0402]  49.59 105.02 180 top
R31  1K_5%_2  [R0201]  50.86 105.02 270 top
R32  33_5%_2  [R0201]  56.88 105.02 90 bottom
R33  *Short_0201  [S0201]  58.38 109.92 90 top
R34  *0_5%_6  [R0603]  62.16 106.89 270 top
R37  100K_5%_2  [R0201]  66.23 96 0 bottom
R38  *Short_0603  [S0603]  62.22 104.58 0 top
R39  0_5%_2  [R0201]  58.74 107.17 90 top
R41  *0_5%_6  [R0603]  59.88 105.68 270 top
R44  *0_5%_2  [R0201]  57.34 99.68 90 top
R52  *10K_5%_2  [R0201]  60.13 97.4 0 top
R55  10K_5%_2  [R0201]  61.53 98.67 270 top
R93  *20K_1%_2  [R0201]  16.88 88.76 90 top
R98  *Short_0201  [S0201]  14.79 89.27 0 top
R104  5.9K_1%_4  [R0402]  18.98 74.15 0 bottom
R106  2.2K_5%_2  [R0201]  21.78 83.3 0 top
R107  2.2K_5%_2  [R0201]  20.76 83.3 180 top
R128  *10K_1%_4  [R0402]  115 34.91 180 top
R129  *HDT@1K_1%_2  [R0201]  111.14 43.04 90 bottom
R130  *100K_1%_4  [R0402]  117.54 40.63 0 top
R131  1K_1%_4  [R0402]  105.85 28.18 0 top
R163  2.2K_5%_2  [R0201]  18.35 84.82 270 top
R164  2.2K_5%_2  [R0201]  19.24 84.82 270 top
R198  *Short_0201  [S0201]  22.67 58.66 0 top
R200  *Short_0201  [S0201]  22.67 57.64 0 top
R210  0_5%_2  [R0201]  21.14 52.44 0 top
R211  *0_5%_2  [R0201]  21.6 52.44 180 top
R217  0_5%_2  [R0201]  21.14 51.68 0 top
R218  *0_5%_2  [R0201]  21.6 51.68 180 top
R222  10K_5%_2  [R0201]  23.43 50.05 0 top
R223  39K_1%_2  [R0201]  16.7 48.5 270 top
R224  *10K_5%_2  [R0201]  207.71 37.58 90 bottom
R225  10K_5%_2  [R0201]  23.43 48.88 0 top
R227  4.7K_5%_2  [R0201]  206.44 37.45 0 bottom
R232  62_1%_4  [R0402]  209.1 37.58 0 bottom
R234  100K_5%_2  [R0201]  23.43 47.66 0 top
R235  20K_1%_2  [R0201]  16.7 47.23 90 top
R238  62_1%_4  [R0402]  210.88 37.58 0 bottom
R244  *TPC@4.7K_5%_2  [R0201]  25.97 14.97 270 top
R246  0_5%_2  [R0201]  21.14 44.56 180 top
R247  0_5%_2  [R0201]  21.14 45.45 180 top
R248  4.7K_5%_2  [R0201]  209.1 36.18 270 bottom
R249  *10K_5%_2  [R0201]  210.63 36.18 0 bottom
R251  *0_5%_2  [R0201]  21.59 44.56 0 top
R252  *0_5%_2  [R0201]  21.59 45.45 0 top
R257  2.2K_5%_2  [R0201]  209.23 35.17 0 bottom
R260  2.2K_5%_2  [R0201]  209.23 33.26 0 bottom
R264  *TPC@4.7K_5%_2  [R0201]  16.19 19.93 270 top
R275  *0_5%_2  [R0201]  206.31 21.96 0 top
R280  *Short_0201  [S0201]  23.05 38.85 0 top
R281  *Short_0201  [S0201]  209.36 26 180 top
R284  *Short_0201  [S0201]  23.05 37.83 0 top
R289  *0_5%_2  [R0201]  209.74 28.94 0 top
R293  *Short_0201  [S0201]  23.18 35.39 0 top
R298  *Short_0201  [S0201]  23.18 36.18 0 top
R309  *10K_1%_2  [R0201]  164.15 32.37 0 top
R310  33_5%_2  [R0201]  164.15 31.61 180 top
R312  22_1%_4  [R0402]  160.46 31.48 270 top
R313  *0_5%_4  [R0402]  205.55 18.4 90 bottom
R314  4.7K_5%_2  [R0201]  172.02 32.5 0 top
R315  4.7K_5%_2  [R0201]  172.15 31.58 90 top
R318  33_5%_2  [R0201]  182.31 29.83 0 top
R319  *Short_0201  [S0201]  177.76 32.09 90 top
R320  *Short_0201  [S0201]  178.5 32.09 90 top
R321  *Short_0201  [S0201]  180.38 31.86 90 top
R322  *Short_0201  [S0201]  181.11 31.86 90 top
R323  22_1%_4  [R0402]  159.19 31.48 270 top
R324  100K_1%_4  [R0402]  161.48 29.7 270 top
R325  *10K_1%_2  [R0201]  168.08 31.86 90 top
R331  *0_5%_2  [R0201]  176.46 31.61 180 top
R333  10K_1%_2  [R0201]  181.93 31.61 90 top
R335  22_1%_4  [R0402]  161.48 31.48 90 top
R336  *0_5%_2  [R0201]  161.61 19.55 90 top
R338  *0_5%_2  [R0201]  200.72 23.35 0 top
R344  0_5%_2  [R0201]  176.46 32.37 180 top
R345  *Short_0201  [S0201]  209.74 30.21 180 top
R348  100K_5%_2  [R0201]  170.34 31.74 90 top
R351  100K_1%_4  [R0402]  160.08 24.12 0 bottom
R355  *10K_5%_2  [R0201]  199.83 21.83 180 top
R358  0_5%_6  [R0603]  163.64 29.32 0 top
R360  *100K_1%_2  [R0201]  199.96 32.24 90 top
R362  10K_1%_2  [R0201]  175.45 31.61 180 top
R363  22_1%_4  [R0402]  160.08 23.1 180 bottom
R364  1K_5%_2  [R0201]  199.83 21.07 180 top
R365  1K_5%_2  [R0201]  177.73 22.47 0 bottom
R366  *Short_0201  [S0201]  201.86 23.35 0 top
R368  33_5%_2  [R0201]  161.48 34.53 180 top
R369  10K_5%_2  [R0201]  162.37 19.55 270 top
R370  10K_5%_2  [R0201]  177.73 23.23 180 bottom
R371  10K_5%_2  [R0201]  181.04 25.89 90 bottom
R373  *0_5%_4  [R0402]  197.8 29.07 90 top
R374  *Short_0402  [S0402]  197.8 26.4 0 top
R375  *Short_0201  [S0201]  197.8 25.13 0 top
R376  MD@10K_5%_2  [R0201]  97.85 37.07 270 top
R382  22_1%_4  [R0402]  161.99 24.37 0 bottom
R384  0_5%_4  [R0402]  164.65 27.29 180 bottom
R385  MD@10K_5%_2  [R0201]  107 43.04 90 top
R389  MD@10K_5%_2  [R0201]  98.61 37.2 90 top
R392  MD@10K_5%_2  [R0201]  107 41.9 90 top
R393  33_5%_2  [R0201]  185.23 28.18 270 top
R399  100K_5%_2  [R0201]  169.86 20.43 270 bottom
R400  *TPM@0_5%_2  [R0201]  121.14 22.59 270 top
R401  2.2_5%_0603  [R0603]  171.64 20.44 180 bottom
R402  33_5%_2  [R0201]  185.53 24.24 270 top
R403  *TPM@33_5%_2  [R0201]  121.6 21.7 0 top
R407  100K_5%_2  [R0201]  185.18 21.5 180 top
R410  33_5%_2  [R0201]  185.13 23.1 180 top
R411  *TPM@10K_1%_2  [R0201]  120.58 20.94 180 top
R412  *TPM@0_5%_2  [R0201]  121.6 20.94 0 top
R416  *Short_0201  [S0201]  185.13 22.29 180 top
R417  *TPM@33_5%_2  [R0201]  120.58 20.18 0 top
R418  *PBA@10K_1%_2  [R0201]  53.12 17.69 180 bottom
R419  *22_5%_2  [R0201]  164.02 21.7 180 bottom
R420  *TPM@0_5%_6  [R0603]  132.95 21.2 0 top
R421  100K_5%_2  [R0201]  183.58 21.32 270 top
R422  *PBA@0_5%_2  [R0201]  51.5 22.59 180 bottom
R423  *TPM@1.2K_5%_2  [R0201]  129.73 20.31 180 top
R429  4.7K_5%_2  [R0201]  72.58 20.94 0 top
R430  33_5%_2  [R0201]  174.94 19.16 90 bottom
R431  *GS@0_5%_2  [R0201]  60.77 19.93 270 top
R432  *TPM@0_5%_6  [R0603]  132.95 22.72 0 top
R435  4.7K_5%_2  [R0201]  204.66 18.27 180 top
R436  *4.7K_5%_2  [R0201]  206.18 18.27 180 top
R437  *Short_0201  [S0201]  70.93 16.12 0 top
R438  *PBA@0_5%_2  [R0201]  52.64 22.59 0 bottom
R440  100K_5%_2  [R0201]  162.24 21.07 90 top
R441  *0_5%_2  [R0201]  162.62 21.2 0 bottom
R442  *Short_0603  [S0603]  115.25 18.15 270 top
R443  *Short_0603  [S0603]  116.67 18.15 270 top
